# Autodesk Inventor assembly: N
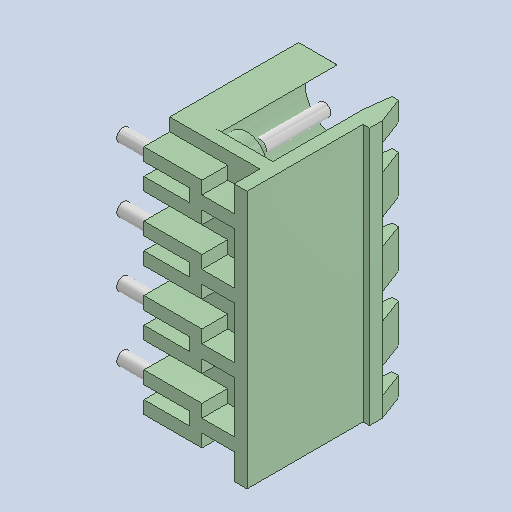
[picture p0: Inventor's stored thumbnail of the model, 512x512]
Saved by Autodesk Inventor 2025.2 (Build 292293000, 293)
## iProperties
Created: 2025-04
Part Number: N
Description: PART--DESC
Document SubType Name: Assembly
Designer: BennF
Author: BennF
Revision Number: NONE
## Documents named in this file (3)
- C:\Users\BennF\Nextcloud\Benutzer\CNC JarBeRi\existing parts\Electronics\RepRap A4988 Shied (USE WITHOUT ARDUINO)\reprap-a4988-1.snapshot.1\RepRap\RepRap\N.iam
- C:\Users\BennF\Nextcloud\Benutzer\CNC JarBeRi\existing parts\Electronics\RepRap A4988 Shied (USE WITHOUT ARDUINO)\reprap-a4988-1.snapshot.1\RepRap\RepRap\N Geometry.ipt
- C:\Users\BennF\Nextcloud\Benutzer\CNC JarBeRi\existing parts\Electronics\RepRap A4988 Shied (USE WITHOUT ARDUINO)\reprap-a4988-1.snapshot.1\RepRap\RepRap\pin.ipt
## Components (2 placed, 2 different names)
1. N Geometry
2. pin
